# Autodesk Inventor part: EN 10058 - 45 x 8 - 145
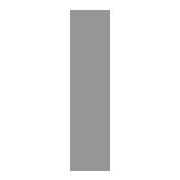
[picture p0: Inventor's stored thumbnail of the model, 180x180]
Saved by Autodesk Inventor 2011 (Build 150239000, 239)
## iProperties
_CCFamilyMember: 49
_CCFamilyDisplayName: DIN EN 10058 - Hot rolled flat steel bars for general purposes
_FrameMemberDoc: Frame Member File
_Version: 15.0.0
_GetPNFromCC: 1
Created: 2010-02
Part Number: EN 10058 - 45 x 8 - 145
Material: Steel, Mild
Description: flat steel bar 45*8
Document SubType Name: Modeling
Standard: DIN
Designer: PC
Standard Revision: 2004
Standards Organization: DIN
Language: en-US
Size Designation: 45 x 8
Categories: <MemberInstance><Categories><Category DisplayName="Structural Shapes" InternalName="089c4875-fa83-4c05-b084-43b9cc11f5ed" Mnemonic="GRDR"><CategoryParameter Dis
Stock Number: 45 x 8
Density: 7.86 g/cm^3
G_L: 145.000 mm
G_W: 8.000 mm
G_H: 45.000 mm
IsCustomPart: 1
Author: PC
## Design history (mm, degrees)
node "Start plane"
node "End plane"
sketch "Sketch"
  geometry: L1 (4, -22.5)-(-4, -22.5); L2 (-4, -22.5)-(-4, 22.5); L3 (-4, 22.5)-(4, 22.5); L4 (4, 22.5)-(4, -22.5); L5 (-6, 0)-(8, 0); L6 (0, -30)-(0, 40); L7 (0, 54)-(0, -44) reference; L8 (-9.2, 0)-(13.2, 0) reference
  constraints: 12 end point, 2 collinear, 2 parallel, 1 horizontal, 1 perpendicular
  dimensions: "d0" = 45 distance between parallel lines of L3 L1 (= G_W); "d1" = 8 distance between parallel lines of L4 L2 (= G_H); "d4" = 4 distance between parallel lines of L6 L4 (= 0.5 x d1); "d5" = 22.5 distance between parallel lines of L5 L3 (= 0.5 x d0)
extrude "Body" new body sketch "Sketch" stored distance "d2" = 145 (= G_L); taper "d3" = 0 deg
node "Driven Length"
  sketch "Sketch3"
    geometry: L1 (0, 0)-(10, 0) reference
    constraints: 2 end point, 1 horizontal
  workplane "Work Plane3"
  sketch "Sketch4"
    geometry: L1 (-2, 0)-(12, 0) reference; L2 (-2, 145)-(12, 145) reference
    dimensions: "d9" = 145 distance between parallel lines of L1 L2 (derived)
body "Solid1"
other parameters: "G_W" = 45 [user parameter; used in 1 equation term], "G_H" = 8 [user parameter; used in 1 equation term], "G_L" = 145 (= d9) [user parameter; used in 1 equation term], "G_OFFSET_START" = 0 [user parameter; used in 1 equation term], "G_OFFSET_END" = 0 [user parameter; used in 1 equation term], "d6" = 0 (computed from G_OFFSET_START), "d7" = 145 (= G_OFFSET_END + B_L), "B_L" = 145 [user parameter; used in 1 equation term], "d8" = 90 deg, "MAS" = 0.283 [user parameter]
